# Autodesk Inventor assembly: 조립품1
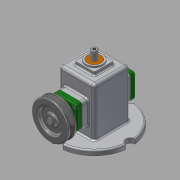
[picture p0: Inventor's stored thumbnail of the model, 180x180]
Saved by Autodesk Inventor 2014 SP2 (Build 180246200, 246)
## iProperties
Created: 2018-07
Part Number: 조립품1
Document SubType Name: Assembly
Designer: 거성
Author: 거성
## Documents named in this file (16)
- C:\Users\거성\Desktop\480708V1010\조립품1.iam
- C:\Users\거성\Desktop\480708V1010\본체.ipt
- C:\Users\거성\Desktop\480708V1010\편심축.ipt
- C:\Users\거성\Desktop\480708V1010\베어링 12x32x10.ipt
- C:\Users\거성\Desktop\480708V1010\뒤커버.ipt
- C:\Users\거성\Desktop\480708V1010\앞커버.ipt
- C:\Users\거성\Desktop\480708V1010\오일 실 12 25 7.ipt
- C:\Users\거성\Desktop\480708V1010\볼트 M4.ipt
- C:\Users\거성\Desktop\480708V1010\링크.ipt
- C:\Users\거성\Desktop\480708V1010\슬라이드.ipt
- C:\Users\거성\Desktop\480708V1010\고정핀 1.2x8.ipt
- C:\Users\거성\Desktop\480708V1010\핀 5x18.ipt
- C:\Users\거성\Desktop\480708V1010\부시.ipt
- C:\Users\거성\Desktop\480708V1010\키 4x4x10.ipt
- C:\Users\거성\Desktop\480708V1010\V벨트풀리.ipt
- C:\Users\거성\Desktop\480708V1010\멈춤나사 M3x8.ipt
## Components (3 placed, 3 different names)
1. 고정핀 1.2x8:1
2. 핀 5x18:1
3. V벨트풀리:1 — 각도:2, 플러쉬:1
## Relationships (2: Angle 1, Flush 1)
- 각도:2 [Angle]: V벨트풀리:1
- 플러쉬:1 [Flush]: V벨트풀리:1
